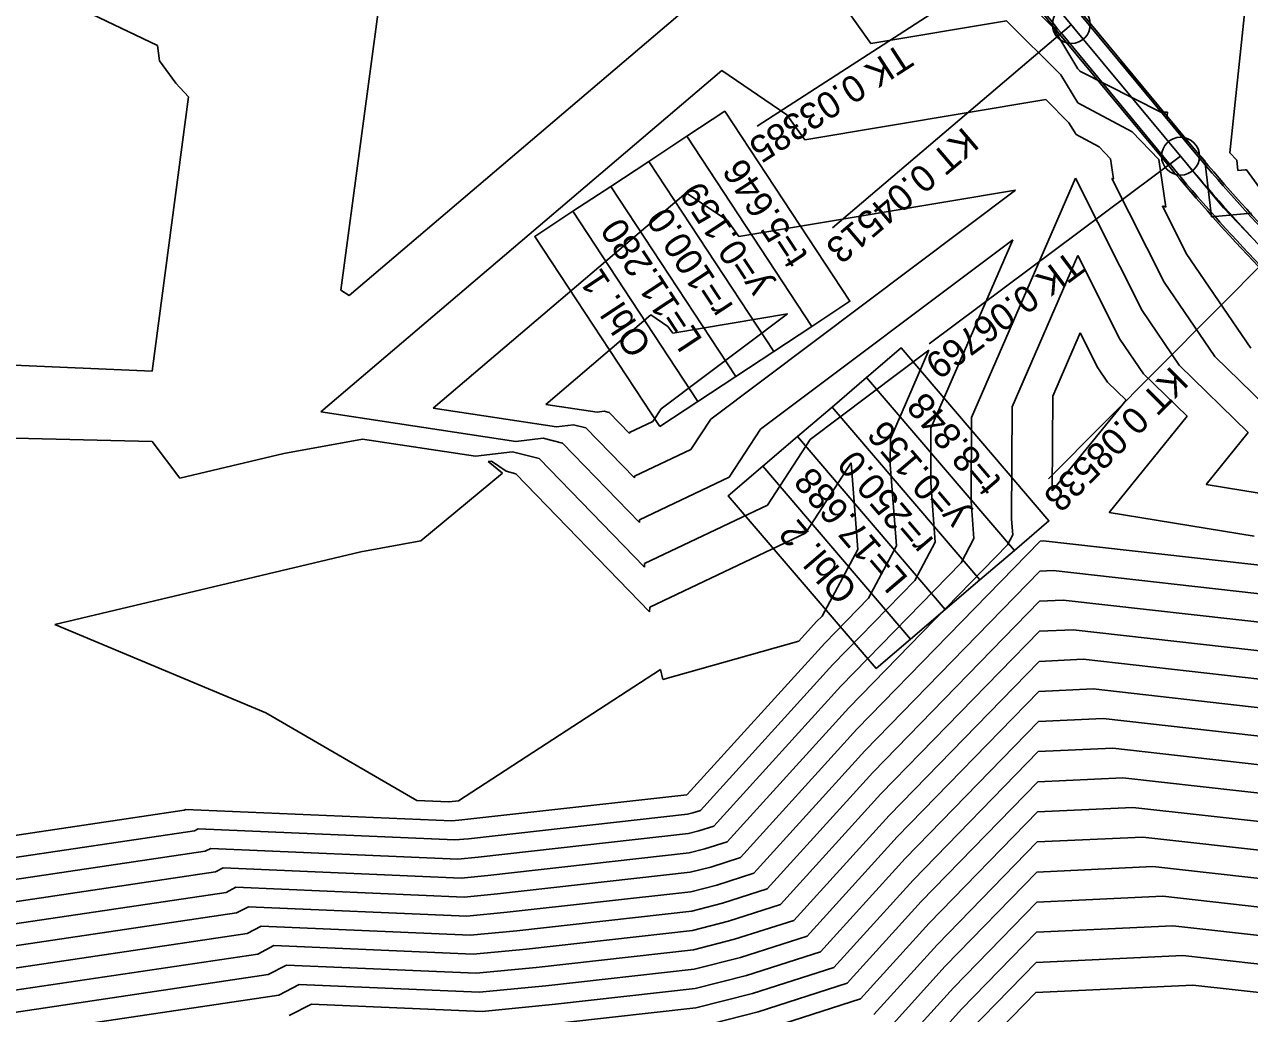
# Model space of a CAD drawing. Extents: x -549394 to -546608, y -1037055 to -1033629.
# Drawn here: x -547214.8 to -547053.3, y -1035925.1 to -1035794.7 of the extents above; entities that cross this region are included whole.
import ezdxf

# ---------------------------------------------------------------- set-up
doc = ezdxf.new("R2010")
doc.units = 0
for name, color, linetype in [('hlavni_vrst', 7, 'Continuous'), ('norm_vrst', 7, 'Continuous'), ('POLYGONY_SITUACE_PO', 7, 'Continuous'), ('x_navrh_C31', 7, 'Continuous'), ('x_osa_C31', 7, 'Continuous'), ('x_popis_oblouky_C31', 7, 'Continuous')]:
    doc.layers.add(name, color=color, linetype=linetype)

msp = doc.modelspace()

# ---------------------------------------------------------------- linework, layer by layer
at = {"layer": 'hlavni_vrst'}
for p, q in [((-547076.25, -1035814.96), (-547089.94, -1035846.53)), ((-547067.45, -1035832.43), (-547076.25, -1035814.96)), ((-547127.56, -1035816.88), (-547160.93, -1035845.29)), ((-547122.14, -1035820.56), (-547127.56, -1035816.88)), ((-547124.34, -1035846.72), (-547084.14, -1035816.55)), ((-547084.14, -1035816.55), (-547120.64, -1035822.65)), ((-547120.64, -1035822.65), (-547122.14, -1035820.56)), ((-547062.56, -1035839.62), (-547067.45, -1035832.43)), ((-547053.44, -1035848.5), (-547062.56, -1035839.62)), ((-547160.93, -1035845.29), (-547144.68, -1035847.74)), ((-547144.68, -1035847.74), (-547142.43, -1035847.47)), ((-547142.43, -1035847.47), (-547140.8, -1035847.89)), ((-547126.94, -1035850.73), (-547124.34, -1035846.72)), ((-547089.94, -1035846.53), (-547090, -1035857.55)), ((-547140.8, -1035847.89), (-547134.4, -1035854.49)), ((-547059.01, -1035855.36), (-547053.44, -1035848.5)), ((-547134.4, -1035854.27), (-547126.94, -1035850.73)), ((-547134.4, -1035854.49), (-547134.4, -1035854.27)), ((-547026.55, -1035860.67), (-547059.01, -1035855.36)), ((-547090, -1035857.55), (-547089.62, -1035862.49)), ((-547089.62, -1035862.49), (-547091.33, -1035865.67)), ((-547091.33, -1035865.67), (-547107.19, -1035881.95)), ((-547081, -1035874.72), (-547101.89, -1035896.16)), ((-547076.55, -1035874.51), (-547081, -1035874.72)), ((-547029.05, -1035879.86), (-547076.55, -1035874.51)), ((-547107.19, -1035881.95), (-547123.92, -1035900.4)), ((-547069.97, -1035894.04), (-547081.19, -1035894.56)), ((-547035.55, -1035897.91), (-547069.97, -1035894.04)), ((-547081.19, -1035894.56), (-547096.58, -1035910.36)), ((-547101.89, -1035896.16), (-547115.13, -1035910.76)), ((-547123.92, -1035900.4), (-547125.91, -1035901.04)), ((-547127.29, -1035901.39), (-547155.01, -1035904.49)), ((-547125.91, -1035901.04), (-547127.29, -1035901.39)), ((-547191.02, -1035903.73), (-547234.27, -1035910.17)), ((-547190.28, -1035903.35), (-547191.02, -1035903.73)), ((-547157.67, -1035904.75), (-547190.28, -1035903.35)), ((-547155.01, -1035904.49), (-547157.67, -1035904.75)), ((-547096.58, -1035910.36), (-547106.34, -1035921.13)), ((-547115.13, -1035910.76), (-547121.98, -1035912.96)), ((-547121.98, -1035912.96), (-547126.73, -1035914.17)), ((-547063.4, -1035913.56), (-547081.38, -1035914.41)), ((-547042.05, -1035915.97), (-547063.4, -1035913.56)), ((-547126.73, -1035914.17), (-547148.65, -1035916.62)), ((-547081.38, -1035914.41), (-547091.28, -1035924.57)), ((-547181.96, -1035916.17), (-547184.08, -1035917.28)), ((-547155.68, -1035917.31), (-547181.96, -1035916.17)), ((-547148.65, -1035916.62), (-547155.68, -1035917.31)), ((-547184.08, -1035917.28), (-547219.2, -1035922.5)), ((-547106.34, -1035921.13), (-547118.06, -1035924.88)), ((-547118.06, -1035924.88), (-547126.18, -1035926.95)), ((-547091.28, -1035924.57), (-547097.55, -1035931.49))]:
    msp.add_line(p, q, dxfattribs=at)
at = {"layer": 'norm_vrst'}
for p, q in [((-547197.3, -1035797.44), (-547264.33, -1035765.41)), ((-547079.24, -1035795.04), (-547090.47, -1035783.78)), ((-547173.1, -1035829.73), (-547167.12, -1035784.94)), ((-547118.23, -1035784.65), (-547172, -1035830.44)), ((-547103.21, -1035797.19), (-547106.48, -1035792.64)), ((-547085.31, -1035794.19), (-547103.21, -1035797.19)), ((-547078.18, -1035801.34), (-547085.31, -1035794.19)), ((-547055.88, -1035811.62), (-547053.89, -1035792.84)), ((-547075.91, -1035800.52), (-547079.24, -1035795.04)), ((-547197.02, -1035799.47), (-547197.3, -1035797.44)), ((-547194.88, -1035802.45), (-547197.02, -1035799.47)), ((-547122.89, -1035800.77), (-547175.77, -1035845.79)), ((-547114.31, -1035806.6), (-547122.89, -1035800.77)), ((-547075.67, -1035800.82), (-547075.91, -1035800.52)), ((-547075.93, -1035805.04), (-547078.18, -1035801.34)), ((-547075.64, -1035800.85), (-547075.67, -1035800.82)), ((-547065, -1035806.27), (-547075.64, -1035800.85)), ((-547193.19, -1035804.21), (-547194.88, -1035802.45)), ((-547198.02, -1035840.41), (-547193.19, -1035804.21)), ((-547080.15, -1035804.6), (-547111.93, -1035809.92)), ((-547077.12, -1035807.65), (-547080.15, -1035804.6)), ((-547068.74, -1035808.83), (-547075.93, -1035805.04)), ((-547111.93, -1035809.92), (-547114.31, -1035806.6)), ((-547064.08, -1035806.26), (-547065, -1035806.27)), ((-547064.18, -1035807.15), (-547064.08, -1035806.26)), ((-547059.16, -1035812.61), (-547064.18, -1035807.15)), ((-547076.16, -1035809.22), (-547077.12, -1035807.65)), ((-547065.22, -1035812.51), (-547068.74, -1035808.83)), ((-547073.1, -1035810.83), (-547076.16, -1035809.22)), ((-547071.6, -1035812.4), (-547073.1, -1035810.83)), ((-547054.97, -1035812.6), (-547055.88, -1035811.62)), ((-547071.22, -1035815.06), (-547071.6, -1035812.4)), ((-547064.32, -1035818.79), (-547065.22, -1035812.51)), ((-547058.28, -1035820.05), (-547059.16, -1035812.61)), ((-547054.81, -1035813.94), (-547054.97, -1035812.6)), ((-547064.53, -1035828.66), (-547071.42, -1035814.99)), ((-547071.42, -1035814.99), (-547071.22, -1035815.06)), ((-547053.86, -1035813.86), (-547054.81, -1035813.94)), ((-547053.67, -1035813.88), (-547053.86, -1035813.86)), ((-547049.05, -1035820.28), (-547053.67, -1035813.88)), ((-547061.62, -1035824.89), (-547064.78, -1035818.6)), ((-547064.78, -1035818.6), (-547064.32, -1035818.79)), ((-547053, -1035819.58), (-547058.28, -1035820.05)), ((-547117.78, -1035848.06), (-547084.51, -1035823.08)), ((-547084.51, -1035823.08), (-547095.29, -1035847.94)), ((-547053.13, -1035837.36), (-547061.62, -1035824.89)), ((-547075.93, -1035825.16), (-547084.58, -1035845.12)), ((-547070.37, -1035836.2), (-547075.93, -1035825.16)), ((-547172, -1035830.44), (-547173.1, -1035829.73)), ((-547057.84, -1035838.49), (-547064.53, -1035828.66)), ((-547132.23, -1035832.99), (-547146.08, -1035844.79)), ((-547129.98, -1035834.52), (-547132.23, -1035832.99)), ((-547130.89, -1035845.38), (-547114.2, -1035832.85)), ((-547114.2, -1035832.85), (-547129.35, -1035835.39)), ((-547129.35, -1035835.39), (-547129.98, -1035834.52)), ((-547075.61, -1035835.35), (-547079.23, -1035843.71)), ((-547073.28, -1035839.97), (-547075.61, -1035835.35)), ((-547067.27, -1035840.75), (-547070.37, -1035836.2)), ((-547111.23, -1035849.41), (-547095.56, -1035837.64)), ((-547095.56, -1035837.64), (-547100.64, -1035849.35)), ((-547045.37, -1035850.64), (-547057.84, -1035838.49)), ((-547217.26, -1035839.59), (-547198.02, -1035840.41)), ((-547071.99, -1035841.88), (-547073.28, -1035839.97)), ((-547061.51, -1035846.36), (-547067.27, -1035840.75)), ((-547069.57, -1035844.23), (-547071.99, -1035841.88)), ((-547079.23, -1035843.71), (-547079.3, -1035856.21)), ((-547079.3, -1035856.21), (-547069.57, -1035844.23)), ((-547175.77, -1035845.79), (-547150.02, -1035849.68)), ((-547146.08, -1035844.79), (-547139.33, -1035845.8)), ((-547139.33, -1035845.8), (-547138.4, -1035845.69)), ((-547138.4, -1035845.69), (-547137.72, -1035845.86)), ((-547137.72, -1035845.86), (-547135.07, -1035848.61)), ((-547131.97, -1035847.04), (-547130.89, -1035845.38)), ((-547084.58, -1035845.12), (-547084.66, -1035859.95)), ((-547135.07, -1035848.52), (-547131.97, -1035847.04)), ((-547071.8, -1035859.05), (-547061.51, -1035846.36)), ((-547216.13, -1035849.24), (-547198, -1035849.68)), ((-547135.07, -1035848.61), (-547135.07, -1035848.52)), ((-547121.9, -1035854.41), (-547117.78, -1035848.06)), ((-547095.29, -1035847.94), (-547095.33, -1035855.14)), ((-547198, -1035849.68), (-547194.35, -1035854.53)), ((-547180.63, -1035851.28), (-547170.26, -1035849.36)), ((-547170.26, -1035849.36), (-547155.37, -1035851.61)), ((-547150.02, -1035849.68), (-547146.45, -1035849.25)), ((-547146.45, -1035849.25), (-547143.88, -1035849.91)), ((-547143.88, -1035849.91), (-547133.73, -1035860.37)), ((-547116.87, -1035858.09), (-547111.23, -1035849.41)), ((-547100.64, -1035849.35), (-547100.66, -1035852.74)), ((-547194.35, -1035854.53), (-547180.63, -1035851.28)), ((-547155.37, -1035851.61), (-547150.48, -1035851.03)), ((-547153.68, -1035852.31), (-547153.26, -1035852.29)), ((-547151.78, -1035853.88), (-547153.68, -1035852.31)), ((-547153.26, -1035852.29), (-547151.33, -1035853.62)), ((-547150.48, -1035851.03), (-547146.95, -1035851.93)), ((-547146.95, -1035851.93), (-547133.07, -1035866.26)), ((-547162.58, -1035862.79), (-547151.78, -1035853.88)), ((-547151.33, -1035853.62), (-547150.03, -1035853.95)), ((-547150.03, -1035853.95), (-547132.4, -1035872.14)), ((-547111.84, -1035861.78), (-547105.82, -1035852.5)), ((-547105.82, -1035852.5), (-547104.95, -1035863.95)), ((-547100.66, -1035852.74), (-547099.84, -1035863.46)), ((-547133.73, -1035860.03), (-547121.9, -1035854.41)), ((-547095.33, -1035855.14), (-547094.73, -1035862.98)), ((-547133.06, -1035865.78), (-547116.87, -1035858.09)), ((-547133.73, -1035860.37), (-547133.73, -1035860.03)), ((-547084.66, -1035859.95), (-547084.51, -1035862.01)), ((-547052.67, -1035862.17), (-547071.8, -1035859.05)), ((-547132.39, -1035871.54), (-547111.84, -1035861.78)), ((-547084.51, -1035862.01), (-547085.22, -1035863.32)), ((-547170.49, -1035864.25), (-547162.58, -1035862.79)), ((-547085.22, -1035863.32), (-547106.13, -1035884.79)), ((-547080.89, -1035862.81), (-547105.07, -1035887.63)), ((-547099.84, -1035863.46), (-547103.55, -1035870.36)), ((-547094.73, -1035862.98), (-547097.44, -1035868.01)), ((-547080.5, -1035862.79), (-547080.89, -1035862.81)), ((-547025.15, -1035869.03), (-547080.5, -1035862.79)), ((-547210.83, -1035873.81), (-547170.49, -1035864.25)), ((-547104.95, -1035863.95), (-547109.66, -1035872.7)), ((-547133.07, -1035866.26), (-547133.06, -1035865.78)), ((-547080.93, -1035866.78), (-547104.01, -1035890.48)), ((-547079.18, -1035866.7), (-547080.93, -1035866.78)), ((-547026.45, -1035872.64), (-547079.18, -1035866.7)), ((-547097.44, -1035868.01), (-547108.25, -1035879.11)), ((-547132.4, -1035872.14), (-547132.39, -1035871.54)), ((-547103.55, -1035870.36), (-547109.31, -1035876.27)), ((-547080.97, -1035870.75), (-547102.95, -1035893.32)), ((-547077.87, -1035870.6), (-547080.97, -1035870.75)), ((-547027.75, -1035876.25), (-547077.87, -1035870.6)), ((-547110.37, -1035873.43), (-547112.7, -1035876)), ((-547109.66, -1035872.7), (-547110.37, -1035873.43)), ((-547183, -1035885.49), (-547210.83, -1035873.81)), ((-547112.7, -1035876), (-547130.65, -1035881.06)), ((-547109.31, -1035876.27), (-547127.43, -1035896.25)), ((-547130.98, -1035879.77), (-547157.61, -1035897.08)), ((-547130.65, -1035881.06), (-547130.98, -1035879.77)), ((-547108.25, -1035879.11), (-547125.67, -1035898.33)), ((-547081.04, -1035878.69), (-547100.82, -1035899)), ((-547075.24, -1035878.41), (-547081.04, -1035878.69)), ((-547030.35, -1035883.47), (-547075.24, -1035878.41)), ((-547081.08, -1035882.66), (-547099.76, -1035901.84)), ((-547073.92, -1035882.32), (-547081.08, -1035882.66)), ((-547031.65, -1035887.08), (-547073.92, -1035882.32)), ((-547163.1, -1035897.04), (-547183, -1035885.49)), ((-547106.13, -1035884.79), (-547122.16, -1035902.47)), ((-547072.6, -1035886.22), (-547081.12, -1035886.63)), ((-547032.95, -1035890.69), (-547072.6, -1035886.22)), ((-547105.07, -1035887.63), (-547120.4, -1035904.55)), ((-547081.12, -1035886.63), (-547098.7, -1035904.68)), ((-547104.01, -1035890.48), (-547118.64, -1035906.62)), ((-547081.15, -1035890.59), (-547097.64, -1035907.52)), ((-547071.29, -1035890.13), (-547081.15, -1035890.59)), ((-547034.25, -1035894.3), (-547071.29, -1035890.13)), ((-547102.95, -1035893.32), (-547116.89, -1035908.69)), ((-547158.86, -1035897.22), (-547163.1, -1035897.04)), ((-547158.83, -1035897.22), (-547158.86, -1035897.22)), ((-547157.61, -1035897.08), (-547158.83, -1035897.22)), ((-547127.51, -1035896.28), (-547157.56, -1035899.64)), ((-547127.48, -1035896.27), (-547127.51, -1035896.28)), ((-547127.43, -1035896.25), (-547127.48, -1035896.27)), ((-547193.8, -1035898.32), (-547240.29, -1035905.23)), ((-547193.61, -1035898.22), (-547193.8, -1035898.32)), ((-547158.47, -1035899.73), (-547193.61, -1035898.22)), ((-547127.4, -1035898.83), (-547156.28, -1035902.07)), ((-547126.7, -1035898.65), (-547127.4, -1035898.83)), ((-547125.67, -1035898.33), (-547126.7, -1035898.65)), ((-547100.82, -1035899), (-547113.37, -1035912.84)), ((-547081.23, -1035898.53), (-547095.52, -1035913.21)), ((-547068.66, -1035897.94), (-547081.23, -1035898.53)), ((-547036.85, -1035901.52), (-547068.66, -1035897.94)), ((-547191.94, -1035900.78), (-547192.41, -1035901.02)), ((-547158.07, -1035902.24), (-547191.94, -1035900.78)), ((-547157.56, -1035899.64), (-547158.47, -1035899.73)), ((-547192.41, -1035901.02), (-547237.28, -1035907.7)), ((-547156.28, -1035902.07), (-547158.07, -1035902.24)), ((-547122.16, -1035902.47), (-547125.13, -1035903.42)), ((-547099.76, -1035901.84), (-547111.61, -1035914.91)), ((-547081.27, -1035902.5), (-547094.46, -1035916.05)), ((-547067.34, -1035901.85), (-547081.27, -1035902.5)), ((-547038.15, -1035905.14), (-547067.34, -1035901.85)), ((-547127.18, -1035903.95), (-547153.74, -1035906.92)), ((-547125.13, -1035903.42), (-547127.18, -1035903.95)), ((-547120.4, -1035904.55), (-547124.34, -1035905.81)), ((-547098.7, -1035904.68), (-547109.86, -1035916.98)), ((-547066.03, -1035905.75), (-547081.31, -1035906.47)), ((-547039.45, -1035908.75), (-547066.03, -1035905.75)), ((-547189.63, -1035906.44), (-547231.25, -1035912.63)), ((-547188.62, -1035905.91), (-547189.63, -1035906.44)), ((-547157.27, -1035907.26), (-547188.62, -1035905.91)), ((-547153.74, -1035906.92), (-547157.27, -1035907.26)), ((-547127.07, -1035906.5), (-547152.47, -1035909.35)), ((-547124.34, -1035905.81), (-547127.07, -1035906.5)), ((-547118.64, -1035906.62), (-547123.55, -1035908.19)), ((-547081.31, -1035906.47), (-547093.4, -1035918.89)), ((-547186.95, -1035908.48), (-547188.25, -1035909.15)), ((-547156.87, -1035909.77), (-547186.95, -1035908.48)), ((-547123.55, -1035908.19), (-547126.96, -1035909.06)), ((-547116.89, -1035908.69), (-547122.77, -1035910.58)), ((-547097.64, -1035907.52), (-547108.1, -1035919.06)), ((-547188.25, -1035909.15), (-547228.24, -1035915.1)), ((-547152.47, -1035909.35), (-547156.87, -1035909.77)), ((-547126.96, -1035909.06), (-547151.19, -1035911.77)), ((-547122.77, -1035910.58), (-547126.85, -1035911.61)), ((-547081.34, -1035910.44), (-547092.34, -1035921.73)), ((-547064.71, -1035909.66), (-547081.34, -1035910.44)), ((-547040.75, -1035912.36), (-547064.71, -1035909.66)), ((-547186.86, -1035911.86), (-547225.23, -1035917.57)), ((-547185.29, -1035911.04), (-547186.86, -1035911.86)), ((-547156.48, -1035912.28), (-547185.29, -1035911.04)), ((-547151.19, -1035911.77), (-547156.48, -1035912.28)), ((-547126.85, -1035911.61), (-547149.92, -1035914.2)), ((-547183.62, -1035913.61), (-547185.47, -1035914.57)), ((-547156.08, -1035914.79), (-547183.62, -1035913.61)), ((-547113.37, -1035912.84), (-547121.2, -1035915.34)), ((-547095.52, -1035913.21), (-547104.58, -1035923.2)), ((-547185.47, -1035914.57), (-547222.21, -1035920.04)), ((-547149.92, -1035914.2), (-547156.08, -1035914.79)), ((-547121.2, -1035915.34), (-547126.62, -1035916.73)), ((-547111.61, -1035914.91), (-547120.41, -1035917.73)), ((-547126.62, -1035916.73), (-547147.37, -1035919.05)), ((-547109.86, -1035916.98), (-547119.63, -1035920.11)), ((-547094.46, -1035916.05), (-547102.83, -1035925.27)), ((-547120.41, -1035917.73), (-547126.51, -1035919.28)), ((-547081.42, -1035918.38), (-547090.22, -1035927.41)), ((-547062.08, -1035917.47), (-547081.42, -1035918.38)), ((-547043.35, -1035919.58), (-547062.08, -1035917.47)), ((-547182.7, -1035919.99), (-547216.19, -1035924.97)), ((-547180.3, -1035918.74), (-547182.7, -1035919.99)), ((-547155.28, -1035919.82), (-547180.3, -1035918.74)), ((-547147.37, -1035919.05), (-547155.28, -1035919.82)), ((-547126.51, -1035919.28), (-547146.1, -1035921.48)), ((-547119.63, -1035920.11), (-547126.4, -1035921.84)), ((-547108.1, -1035919.06), (-547118.84, -1035922.5)), ((-547093.4, -1035918.89), (-547101.07, -1035927.35)), ((-547178.63, -1035921.3), (-547181.31, -1035922.69)), ((-547154.88, -1035922.33), (-547178.63, -1035921.3)), ((-547146.1, -1035921.48), (-547154.88, -1035922.33)), ((-547126.4, -1035921.84), (-547144.83, -1035923.9)), ((-547092.34, -1035921.73), (-547099.31, -1035929.42)), ((-547060.76, -1035921.37), (-547081.46, -1035922.35)), ((-547044.65, -1035923.19), (-547060.76, -1035921.37)), ((-547181.31, -1035922.69), (-547213.17, -1035927.44)), ((-547118.84, -1035922.5), (-547126.29, -1035924.39)), ((-547104.58, -1035923.2), (-547117.27, -1035927.27)), ((-547081.46, -1035922.35), (-547089.16, -1035930.25)), ((-547176.97, -1035923.87), (-547179.92, -1035925.4)), ((-547154.48, -1035924.84), (-547176.97, -1035923.87)), ((-547144.83, -1035923.9), (-547154.48, -1035924.84)), ((-547126.29, -1035924.39), (-547143.56, -1035926.33))]:
    msp.add_line(p, q, dxfattribs=at)
at = {"layer": 'POLYGONY_SITUACE_PO'}
for centre in [(-547076.78, -1035794.69), (-547062.38, -1035812.06)]:
    msp.add_circle(centre, 2.5, dxfattribs=at)
at = {"layer": 'x_navrh_C31'}
for p, q in [((-547075.44, -1035793.57), (-547061.03, -1035810.94)), ((-547075.24, -1035793.41), (-547060.84, -1035810.78)), ((-547078.13, -1035795.81), (-547063.73, -1035813.18))]:
    msp.add_line(p, q, dxfattribs=at)
for points in [[(-547078.32, -1035795.97), (-547063.92, -1035813.34)], [(-547070.19, -1035799.51), (-547060.84, -1035810.78)]]:
    msp.add_lwpolyline(points, dxfattribs=at)
for centre, radius, start, end in [((-546999.81, -1035730.86), 102, 213.2057, 219.6688), ((-546999.81, -1035730.86), 101.75, 213.2057, 219.6688), ((-546869.94, -1035652.47), 248.25, 219.6688, 223.7225), ((-546869.94, -1035652.47), 248, 219.6688, 223.7225), ((-546869.94, -1035652.47), 252, 219.6688, 223.7225), ((-546869.94, -1035652.47), 251.75, 219.6688, 223.7225)]:
    msp.add_arc(centre, radius, start, end, dxfattribs=at)
at = {"layer": 'x_osa_C31'}
msp.add_lwpolyline([(-547102.02, -1035757.3), (-547080.39, -1035790.35), (-547080.39, -1035790.35), (-547056.73, -1035818.87), (-547022.58, -1035854.58), (-547022.58, -1035854.58), (-547000.23, -1035880.99)], dxfattribs=at)
msp.add_arc((-546869.94, -1035652.47), 250, 219.6688, 223.7225, dxfattribs=at)
at = {"layer": 'x_popis_oblouky_C31'}
for points in [[(-547083.48, -1035785.62), (-547118.21, -1035808.11)], [(-547076.78, -1035794.69), (-547108.28, -1035821.52)], [(-547062.38, -1035812.06), (-547095.53, -1035836.82)], [(-547050.62, -1035825.26), (-547079.8, -1035854.6)]]:
    msp.add_lwpolyline(points, dxfattribs=at)
for points in [[(-547111, -1035834.5), (-547127.49, -1035809.44), (-547122.48, -1035806.14), (-547105.99, -1035831.2)], [(-547116.01, -1035837.8), (-547132.51, -1035812.74), (-547127.49, -1035809.44), (-547111, -1035834.5)], [(-547121.02, -1035841.1), (-547137.52, -1035816.04), (-547132.51, -1035812.74), (-547116.01, -1035837.8)], [(-547126.04, -1035844.39), (-547142.53, -1035819.33), (-547137.52, -1035816.04), (-547121.02, -1035841.1)], [(-547131.05, -1035847.69), (-547147.54, -1035822.63), (-547142.53, -1035819.33), (-547126.04, -1035844.39)], [(-547084.29, -1035864.05), (-547103.78, -1035841.24), (-547099.22, -1035837.34), (-547079.73, -1035860.15)], [(-547088.85, -1035867.94), (-547108.34, -1035845.14), (-547103.78, -1035841.24), (-547084.29, -1035864.05)], [(-547093.41, -1035871.84), (-547112.9, -1035849.04), (-547108.34, -1035845.14), (-547088.85, -1035867.94)], [(-547097.97, -1035875.74), (-547117.46, -1035852.94), (-547112.9, -1035849.04), (-547093.41, -1035871.84)], [(-547102.53, -1035879.64), (-547122.03, -1035856.84), (-547117.46, -1035852.94), (-547097.97, -1035875.74)]]:
    msp.add_lwpolyline(points, close=True, dxfattribs=at)

# ---------------------------------------------------------------- texts
for s, rotation, p in [('TK 0.03385', 212.918, (-547099.27, -1035797.03)), ('KT 0.04513', 220.4188, (-547090.98, -1035808.09)), ('t=5.646', 123.3722, (-547111.37, -1035825.22)), ('y=0.159', 123.3722, (-547116.42, -1035829.1)), ('r=100.0', 123.3722, (-547121.25, -1035831.86)), ('L=11.280', 123.3722, (-547125.31, -1035836.3)), ('TK 0.06769', 216.7513, (-547076.94, -1035824.36)), ('Obl. 1', 123.3722, (-547132, -1035837.05)), ('KT 0.08538', 225.1477, (-547063.59, -1035839.61)), ('t=8.848', 130.5506, (-547085.81, -1035854.89)), ('y=0.156', 130.5506, (-547090.34, -1035859.37)), ('r=250.0', 130.5506, (-547094.79, -1035862.71)), ('L=17.688', 130.5506, (-547098.16, -1035867.74)), ('Obl. 2', 130.5506, (-547104.8, -1035869.2))]:
    msp.add_text(s, height=3.5, rotation=rotation, dxfattribs=at).set_placement(p)

doc.saveas('drawing.dxf')
